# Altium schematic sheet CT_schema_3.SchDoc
size 313 x 185 mm
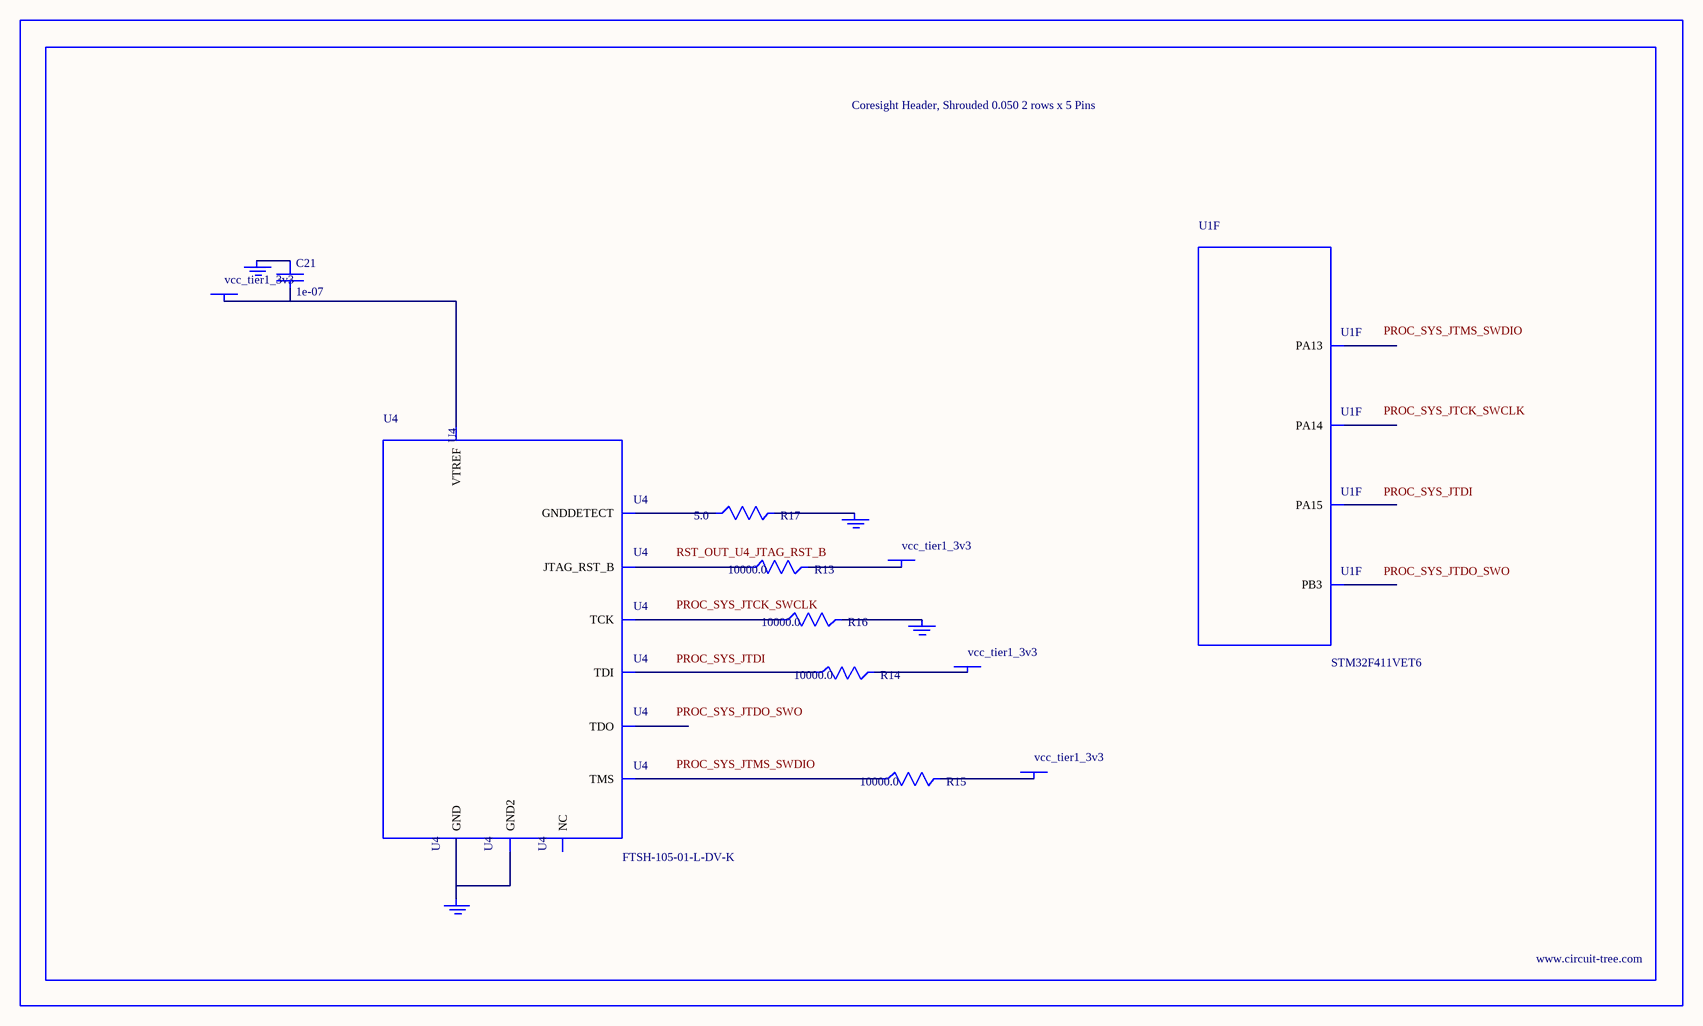
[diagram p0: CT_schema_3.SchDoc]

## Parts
BORDER2  (no value)
C21  1e-07  [C0402]
GND_INSTANCE_2_0  (no value)
GND_INSTANCE_2_1  (no value)
GND_INSTANCE_2_2  (no value)
GND_INSTANCE_2_3  (no value)
POWER_INSTANCE_2_0  vcc_tier1_3v3
POWER_INSTANCE_2_1  vcc_tier1_3v3
POWER_INSTANCE_2_2  vcc_tier1_3v3
POWER_INSTANCE_2_3  vcc_tier1_3v3
R13  10000.0  [R0603]
R14  10000.0  [R0603]
R15  10000.0  [R0603]
R16  10000.0  [R0603]
R17  5.0  [R0603]
U1  STM32F411VET6  [LQFP100]  (part F of 10)
U4  FTSH-105-01-L-DV-K  [SAMTEC_FTSH-105-01-L-DV-K]

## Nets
NetC21_1: C21.1 GND_INSTANCE_2_0.0(GND)
NetC21_2: C21.2 POWER_INSTANCE_2_0.0(PWR) U4.1(VTREF)
NetGND_INSTANCE_2_1_0: GND_INSTANCE_2_1.0(GND) R16.2
NetGND_INSTANCE_2_2_0: GND_INSTANCE_2_2.0(GND) R17.2
NetGND_INSTANCE_2_3_0: GND_INSTANCE_2_3.0(GND) U4.3(GND) U4.5(GND2)
NetPOWER_INSTANCE_2_1_0: POWER_INSTANCE_2_1.0(PWR) R15.2
NetPOWER_INSTANCE_2_2_0: POWER_INSTANCE_2_2.0(PWR) R14.2
NetPOWER_INSTANCE_2_3_0: POWER_INSTANCE_2_3.0(PWR) R13.2
NetR13_1: R13.1 U4.10(JTAG_RST_B)
NetR14_1: R14.1 U4.8(TDI)
NetR15_1: R15.1 U4.2(TMS)
NetR16_1: R16.1 U4.4(TCK)
NetR17_1: R17.1 U4.9(GNDDETECT)

Not connected (* = marked no-connect by the designer): U1 72(PA13) 76(PA14) 77(PA15) 89(PB3); U4 6(TDO) 7(NC)

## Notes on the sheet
- Labels drawn without touching a wire or pin: PROC_SYS_JTCK_SWCLK, PROC_SYS_JTDI, PROC_SYS_JTDO_SWO, PROC_SYS_JTMS_SWDIO, RST_OUT_U4_JTAG_RST_B

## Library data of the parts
BORDER2 = BORDER_PAGE2
C21 = C0402C104K3RACTU
GND_INSTANCE_2_0-GND_INSTANCE_2_3 = GND
POWER_INSTANCE_2_0-POWER_INSTANCE_2_3 = PWR
R13-R16 = RC0603JR-0710KL
R17 = ERJ-3GEYJ5R1V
